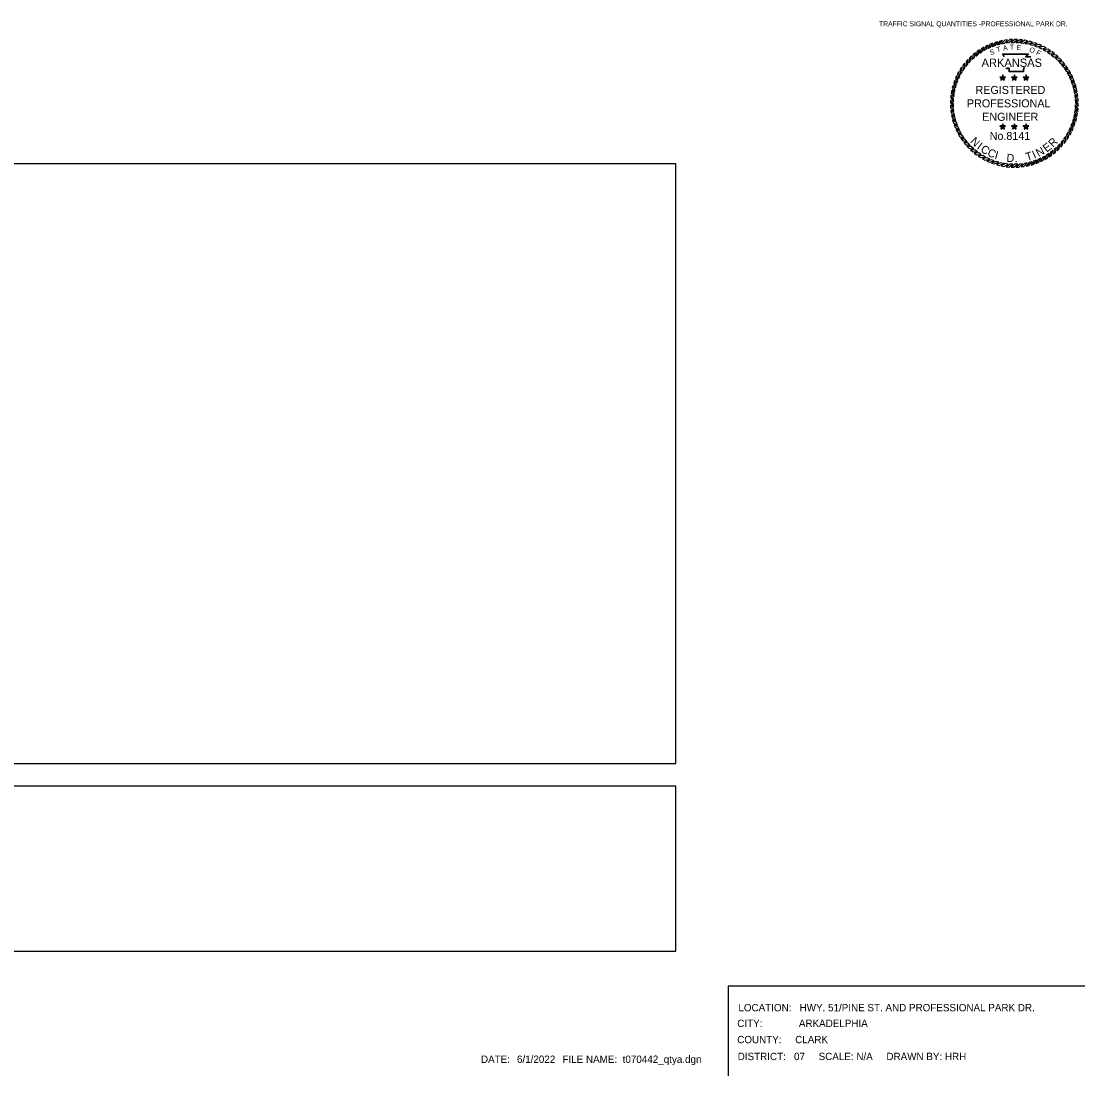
# Model space of a CAD drawing. Extents: x 418532 to 419834, y -565899 to -565297.
# Drawn here: x 419227 to 419834, y -565899 to -565297 of the extents above; entities that cross this region are included whole.
import ezdxf

# ---------------------------------------------------------------- set-up
doc = ezdxf.new("R2010")
doc.units = 0
for name, color, linetype in [('1', 7, 'Continuous'), ('G-ANNO-SYMB', 7, 'Continuous'), ('Level 10', 7, 'Continuous'), ('Level 57', 7, 'Continuous'), ('V-SIGNAL-LOOP', 7, 'Continuous')]:
    doc.layers.add(name, color=color, linetype=linetype)

msp = doc.modelspace()

# ---------------------------------------------------------------- linework, layer by layer
at = {"layer": 'G-ANNO-SYMB'}
for points in [[(419779.1, -565310.34), (419777.68, -565311.01), (419776.5, -565313.54), (419777.98, -565312.72)], [(419781.75, -565309.27), (419780.29, -565309.83), (419778.91, -565312.26), (419780.46, -565311.56)], [(419784.49, -565308.41), (419782.98, -565308.85), (419781.42, -565311.17), (419783.01, -565310.6)], [(419787.28, -565307.77), (419785.74, -565308.1), (419784, -565310.28), (419785.64, -565309.84)], [(419790.11, -565307.35), (419788.56, -565307.56), (419786.65, -565309.6), (419788.32, -565309.28)], [(419792.97, -565307.16), (419791.4, -565307.24), (419789.34, -565309.13), (419791.03, -565308.94)], [(419795.83, -565307.19), (419794.27, -565307.15), (419792.06, -565308.87), (419793.76, -565308.81)], [(419798.69, -565307.45), (419797.13, -565307.28), (419794.8, -565308.82), (419796.49, -565308.9)], [(419801.51, -565307.92), (419799.97, -565307.64), (419797.52, -565308.99), (419799.21, -565309.2)], [(419804.29, -565308.62), (419802.77, -565308.21), (419800.23, -565309.37), (419801.89, -565309.72)], [(419807, -565309.54), (419805.53, -565309.01), (419802.9, -565309.97), (419804.53, -565310.44)], [(419809.64, -565310.66), (419808.21, -565310.02), (419805.51, -565310.77), (419807.1, -565311.37)], [(419769.54, -565316.57), (419768.4, -565317.65), (419768.06, -565320.43), (419769.22, -565319.19)], [(419771.74, -565314.74), (419770.52, -565315.72), (419769.96, -565318.46), (419771.21, -565317.32)], [(419774.07, -565313.08), (419772.78, -565313.96), (419772.01, -565316.65), (419773.35, -565315.61)], [(419776.53, -565311.61), (419775.17, -565312.39), (419774.19, -565315.01), (419775.61, -565314.08)], [(419812.17, -565311.99), (419810.8, -565311.24), (419808.05, -565311.77), (419809.59, -565312.49)], [(419814.6, -565313.51), (419813.29, -565312.65), (419810.51, -565312.97), (419811.98, -565313.81)], [(419816.9, -565315.22), (419815.66, -565314.26), (419812.86, -565314.36), (419814.27, -565315.31)], [(419819.06, -565317.1), (419817.89, -565316.05), (419815.1, -565315.93), (419816.42, -565316.99)], [(419765.61, -565320.73), (419764.65, -565321.98), (419764.75, -565324.77), (419765.7, -565323.37)], [(419767.49, -565318.58), (419766.44, -565319.74), (419766.32, -565322.53), (419767.38, -565321.21)], [(419821.06, -565319.15), (419819.98, -565318.01), (419817.21, -565317.67), (419818.44, -565318.83)], [(419822.9, -565321.35), (419821.91, -565320.13), (419819.17, -565319.57), (419820.31, -565320.82)], [(419824.56, -565323.68), (419823.67, -565322.39), (419820.98, -565321.62), (419822.02, -565322.96)], [(419761.05, -565328), (419760.41, -565329.43), (419761.16, -565332.12), (419761.76, -565330.54)], [(419762.38, -565325.46), (419761.63, -565326.84), (419762.16, -565329.58), (419762.88, -565328.05)], [(419763.9, -565323.03), (419763.05, -565324.35), (419763.36, -565327.12), (419764.2, -565325.65)], [(419787.34, -565329.1), (419786.97, -565328.58), (419785.76, -565328.58), (419786.74, -565329.29)], [(419787.34, -565329.1), (419787.72, -565328.58), (419787.34, -565327.43), (419786.97, -565328.58)], [(419787.34, -565329.1), (419787.95, -565329.29), (419788.93, -565328.58), (419787.72, -565328.58)], [(419794.01, -565329.1), (419793.64, -565328.58), (419792.43, -565328.58), (419793.41, -565329.29)], [(419794.01, -565329.1), (419794.39, -565328.58), (419794.01, -565327.43), (419793.64, -565328.58)], [(419794.01, -565329.1), (419794.62, -565329.29), (419795.6, -565328.58), (419794.39, -565328.58)], [(419800.68, -565329.1), (419800.31, -565328.58), (419799.1, -565328.58), (419800.08, -565329.29)], [(419800.68, -565329.1), (419801.06, -565328.58), (419800.68, -565327.43), (419800.31, -565328.58)], [(419800.68, -565329.1), (419801.29, -565329.29), (419802.27, -565328.58), (419801.06, -565328.58)], [(419826.03, -565326.14), (419825.24, -565324.78), (419822.63, -565323.8), (419823.56, -565325.22)], [(419827.3, -565328.71), (419826.63, -565327.29), (419824.09, -565326.11), (419824.91, -565327.59)], [(419828.37, -565331.36), (419827.81, -565329.9), (419825.37, -565328.52), (419826.07, -565330.06)], [(419759.02, -565333.35), (419758.61, -565334.86), (419759.77, -565337.4), (419760.11, -565335.74)], [(419759.93, -565330.63), (419759.4, -565332.11), (419760.36, -565334.74), (419760.83, -565333.11)], [(419787.34, -565329.1), (419786.74, -565329.29), (419786.36, -565330.45), (419787.34, -565329.73)], [(419787.34, -565329.1), (419787.34, -565329.73), (419788.32, -565330.45), (419787.95, -565329.29)], [(419794.01, -565329.1), (419793.41, -565329.29), (419793.03, -565330.45), (419794.01, -565329.73)], [(419794.01, -565329.1), (419794.01, -565329.73), (419794.99, -565330.45), (419794.62, -565329.29)], [(419800.68, -565329.1), (419800.08, -565329.29), (419799.7, -565330.45), (419800.68, -565329.73)], [(419800.68, -565329.1), (419800.68, -565329.73), (419801.66, -565330.45), (419801.29, -565329.29)], [(419829.22, -565334.1), (419828.78, -565332.59), (419826.46, -565331.03), (419827.04, -565332.62)], [(419829.86, -565336.89), (419829.54, -565335.35), (419827.35, -565333.61), (419827.8, -565335.25)], [(419757.84, -565338.95), (419757.67, -565340.51), (419759.21, -565342.84), (419759.29, -565341.15)], [(419758.32, -565336.12), (419758.03, -565337.66), (419759.38, -565340.11), (419759.59, -565338.43)], [(419830.28, -565339.72), (419830.08, -565338.17), (419828.03, -565336.26), (419828.35, -565337.92)], [(419830.47, -565342.58), (419830.39, -565341.01), (419828.51, -565338.95), (419828.69, -565340.64)], [(419757.58, -565341.8), (419757.54, -565343.37), (419759.26, -565345.57), (419759.21, -565343.88)], [(419757.55, -565344.66), (419757.63, -565346.23), (419759.52, -565348.29), (419759.33, -565346.61)], [(419830.19, -565348.29), (419830.36, -565346.74), (419828.81, -565344.4), (419828.73, -565346.1)], [(419830.44, -565345.44), (419830.49, -565343.87), (419828.77, -565341.67), (419828.82, -565343.37)], [(419757.75, -565347.52), (419757.95, -565349.08), (419759.99, -565350.98), (419759.67, -565349.32)], [(419758.16, -565350.35), (419758.49, -565351.89), (419760.68, -565353.63), (419760.23, -565352)], [(419828.1, -565356.61), (419828.62, -565355.13), (419827.67, -565352.51), (419827.2, -565354.13)], [(419829.01, -565353.9), (419829.42, -565352.38), (419828.26, -565349.84), (419827.92, -565351.5)], [(419829.71, -565351.12), (419830, -565349.58), (419828.64, -565347.13), (419828.43, -565348.81)], [(419758.8, -565353.15), (419759.25, -565354.65), (419761.56, -565356.21), (419760.99, -565354.62)], [(419759.66, -565355.88), (419760.22, -565357.34), (419762.65, -565358.72), (419761.95, -565357.18)], [(419760.73, -565358.54), (419761.4, -565359.95), (419763.93, -565361.14), (419763.12, -565359.65)], [(419787.34, -565357.03), (419786.97, -565356.51), (419785.76, -565356.51), (419786.74, -565357.22)], [(419787.34, -565357.03), (419786.74, -565357.22), (419786.36, -565358.38), (419787.34, -565357.66)], [(419787.34, -565357.03), (419787.72, -565356.51), (419787.34, -565355.36), (419786.97, -565356.51)], [(419787.34, -565357.03), (419787.95, -565357.22), (419788.93, -565356.51), (419787.72, -565356.51)], [(419787.34, -565357.03), (419787.34, -565357.66), (419788.32, -565358.38), (419787.95, -565357.22)], [(419794.01, -565357.03), (419793.64, -565356.51), (419792.43, -565356.51), (419793.41, -565357.22)], [(419794.01, -565357.03), (419793.41, -565357.22), (419793.03, -565358.38), (419794.01, -565357.66)], [(419794.01, -565357.03), (419794.39, -565356.51), (419794.01, -565355.36), (419793.64, -565356.51)], [(419794.01, -565357.03), (419794.62, -565357.22), (419795.6, -565356.51), (419794.39, -565356.51)], [(419794.01, -565357.03), (419794.01, -565357.66), (419794.99, -565358.38), (419794.62, -565357.22)], [(419800.68, -565357.03), (419800.31, -565356.51), (419799.1, -565356.51), (419800.08, -565357.22)], [(419800.68, -565357.03), (419800.08, -565357.22), (419799.7, -565358.38), (419800.68, -565357.66)], [(419800.68, -565357.03), (419801.06, -565356.51), (419800.68, -565355.36), (419800.31, -565356.51)], [(419800.68, -565357.03), (419801.29, -565357.22), (419802.27, -565356.51), (419801.06, -565356.51)], [(419800.68, -565357.03), (419800.68, -565357.66), (419801.66, -565358.38), (419801.29, -565357.22)], [(419825.65, -565361.78), (419826.4, -565360.41), (419825.86, -565357.66), (419825.14, -565359.2)], [(419826.97, -565359.24), (419827.61, -565357.81), (419826.87, -565355.12), (419826.27, -565356.7)], [(419762, -565361.1), (419762.78, -565362.46), (419765.4, -565363.44), (419764.47, -565362.03)], [(419763.47, -565363.56), (419764.36, -565364.85), (419767.04, -565365.63), (419766, -565364.29)], [(419820.53, -565368.67), (419821.58, -565367.5), (419821.71, -565364.71), (419820.65, -565366.03)], [(419822.41, -565366.51), (419823.37, -565365.27), (419823.27, -565362.47), (419822.32, -565363.87)], [(419824.12, -565364.21), (419824.98, -565362.89), (419824.66, -565360.12), (419823.82, -565361.59)], [(419765.13, -565365.9), (419766.11, -565367.12), (419768.85, -565367.67), (419767.71, -565366.42)], [(419766.97, -565368.09), (419768.04, -565369.23), (419770.82, -565369.57), (419769.58, -565368.41)], [(419768.97, -565370.14), (419770.13, -565371.19), (419772.93, -565371.31), (419771.6, -565370.25)], [(419813.95, -565374.16), (419815.25, -565373.28), (419816.02, -565370.59), (419814.68, -565371.63)], [(419816.29, -565372.51), (419817.51, -565371.52), (419818.07, -565368.78), (419816.81, -565369.92)], [(419818.48, -565370.67), (419819.63, -565369.59), (419819.97, -565366.82), (419818.81, -565368.05)], [(419771.13, -565372.02), (419772.37, -565372.98), (419775.16, -565372.88), (419773.76, -565371.93)], [(419773.43, -565373.73), (419774.74, -565374.59), (419777.52, -565374.27), (419776.04, -565373.43)], [(419775.85, -565375.25), (419777.23, -565376), (419779.97, -565375.47), (419778.44, -565374.75)], [(419778.39, -565376.58), (419779.82, -565377.22), (419782.51, -565376.47), (419780.93, -565375.88)], [(419781.02, -565377.7), (419782.5, -565378.23), (419785.13, -565377.28), (419783.5, -565376.8)], [(419800.75, -565379.47), (419802.28, -565379.15), (419804.02, -565376.96), (419802.39, -565377.41)], [(419803.54, -565378.83), (419805.04, -565378.39), (419806.61, -565376.07), (419805.01, -565376.65)], [(419806.27, -565377.97), (419807.74, -565377.42), (419809.11, -565374.98), (419807.57, -565375.68)], [(419808.93, -565376.91), (419810.35, -565376.23), (419811.53, -565373.7), (419810.04, -565374.52)], [(419811.49, -565375.63), (419812.85, -565374.85), (419813.83, -565372.23), (419812.42, -565373.17)], [(419783.74, -565378.62), (419785.25, -565379.03), (419787.8, -565377.87), (419786.14, -565377.53)], [(419786.52, -565379.32), (419788.06, -565379.61), (419790.5, -565378.25), (419788.82, -565378.04)], [(419789.34, -565379.8), (419790.9, -565379.96), (419793.23, -565378.42), (419791.54, -565378.34)], [(419792.19, -565380.05), (419793.76, -565380.1), (419795.96, -565378.37), (419794.27, -565378.43)], [(419795.06, -565380.08), (419796.62, -565380), (419798.68, -565378.11), (419797, -565378.3)], [(419797.91, -565379.89), (419799.47, -565379.69), (419801.38, -565377.64), (419799.71, -565377.96)]]:
    msp.add_lwpolyline(points, close=True, dxfattribs=at)
for points in [[(419788.17, -565317.15), (419787.32, -565315.31), (419802.03, -565315.3), (419800.8, -565316.84), (419801.8, -565316.83), (419802.64, -565316.82), (419803.47, -565316.91)], [(419788.38, -565317.05), (419787.68, -565315.54), (419801.55, -565315.53), (419800.31, -565317.08), (419801.8, -565317.06), (419802.63, -565317.05), (419803.45, -565317.14)], [(419799.71, -565323.31), (419799.46, -565323.52), (419799.38, -565323.82), (419799.3, -565324.59), (419799.3, -565325.6), (419791.08, -565325.6), (419791.08, -565324.23), (419791.08, -565323.92), (419790.75, -565323.82), (419789.58, -565323.82), (419789.37, -565323.51)], [(419799.57, -565323.13), (419799.26, -565323.38), (419799.15, -565323.78), (419799.06, -565324.57), (419799.06, -565325.37), (419791.32, -565325.37), (419791.32, -565324.23), (419791.32, -565323.75), (419790.78, -565323.59), (419789.71, -565323.59), (419789.57, -565323.38)]]:
    msp.add_lwpolyline(points, dxfattribs=at)
at = {"layer": 'Level 57'}
for points in [[(419630.59, -565847.55), (419630.59, -565898.75)], [(419834.17, -565847.55), (419630.59, -565847.55)]]:
    msp.add_lwpolyline(points, dxfattribs=at)
at = {"layer": 'V-SIGNAL-LOOP'}
for points in [[(419105.55, -565720.57), (419600.78, -565720.57), (419600.78, -565378.11), (419105.55, -565378.11)], [(419105.55, -565827.68), (419600.78, -565827.68), (419600.78, -565733.51), (419105.55, -565733.51)]]:
    msp.add_lwpolyline(points, close=True, dxfattribs=at)

# ---------------------------------------------------------------- texts
at = {"layer": '1'}
msp.add_text('TRAFFIC SIGNAL QUANTITIES -PROFESSIONAL PARK DR.', height=2.8, rotation=360, dxfattribs=at).set_placement((419716.78, -565299.6))
at = {"layer": 'G-ANNO-SYMB'}
for s, height, rotation, p in [('A', 2.9, 8.67877, (419787.72, -565313.61)), ('T', 2.9, 1.47887, (419791.47, -565313.03)), ('E', 2.9, 356.67203, (419795.18, -565313.12)), ('S', 2.9, 19.77256, (419780.51, -565316.18)), ('T', 2.9, 16.90148, (419784.2, -565314.53)), ('O', 2.9, 341.2218, (419802.23, -565314.11)), ('F', 2.9, 335.36282, (419806.14, -565315.64)), ('N', 4.59, 315.26758, (419768.53, -565365.62)), ('R', 4.59, 45.47796, (419816.1, -565369.02)), ('I', 4.59, 324.21406, (419772.26, -565369.31)), ('C', 4.59, 328.68731, (419774.33, -565370.93)), ('C', 4.59, 336.51548, (419778.24, -565373.36)), ('I', 4.59, 344.34365, (419782.43, -565375.23)), ('T', 4.59, 16.77466, (419801.19, -565376.51)), ('I', 4.59, 24.23006, (419805.4, -565375.3)), ('N', 4.59, 28.7033, (419807.83, -565374.32)), ('E', 4.59, 37.64979, (419812.44, -565371.79)), ('D', 4.59, 356.64507, (419789.43, -565376.97)), ('.', 4.59, 4.84601, (419794.24, -565377.28))]:
    msp.add_text(s, height=height, rotation=rotation, dxfattribs=at).set_placement(p)
for s, height, p in [('ARKANSAS', 4.737, (419775.29, -565322.78)), ('REGISTERED', 4.585, (419771.85, -565338.25)), ('PROFESSIONAL', 4.5855, (419766.94, -565345.91)), ('ENGINEER', 4.585, (419775.67, -565353.58)), ('No.8141', 4.567, (419779.95, -565364.51))]:
    msp.add_text(s, height=height, dxfattribs=at).set_placement(p)
at = {"layer": 'Level 10'}
for s, p in [('LOCATION:   HWY. 51/PINE ST. AND PROFESSIONAL PARK DR.', (419636.51, -565861.97)), ('CITY:', (419635.87, -565870.93)), (' ARKADELPHIA', (419669.47, -565870.93)), ('COUNTY:     CLARK', (419635.85, -565880.2)), ('DATE:  ', (419489.59, -565891.43)), ('6/1/2022', (419510.13, -565891.43)), ('  FILE NAME: ', (419532.97, -565891.43)), ('t070442_qtya.dgn', (419570.46, -565891.43)), ('DISTRICT:   07     SCALE: N/A     DRAWN BY: HRH', (419636.11, -565889.83))]:
    msp.add_text(s, height=4.2, rotation=360, dxfattribs=at).set_placement(p)

doc.saveas('drawing.dxf')
